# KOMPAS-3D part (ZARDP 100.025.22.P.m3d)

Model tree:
1. Операция без истории:1
2. Операция без истории:2
3. Операция без истории:3
4. Операция без истории:4
5. Операция без истории:5
6. Операция без истории:6
7. Операция без истории:7
8. Операция без истории:8
9. Операция без истории:9
10. Операция без истории:10
11. Операция без истории:11
12. Операция без истории:12
13. Операция без истории:13
14. Операция без истории:14
15. Операция без истории:15
16. Операция без истории:16
17. Операция без истории:17
18. Операция без истории:18
19. Операция без истории:19
20. Операция без истории:20
21. Операция без истории:21
22. Операция без истории:22
23. Операция без истории:23
24. Операция без истории:24
25. Операция без истории:25
26. Операция без истории:26
27. Операция без истории:27
28. Операция без истории:28
29. Операция без истории:29
30. Операция без истории:30
31. Операция без истории:31
32. Операция без истории:32
33. Операция без истории:33
34. Операция без истории:34
35. Операция без истории:35
36. Операция без истории:36
37. Операция без истории:37
38. Операция без истории:38
39. Операция без истории:39
40. Операция без истории:40
41. Операция без истории:41
42. Операция без истории:42
43. Операция без истории:43
44. Операция без истории:44
45. Операция без истории:45
46. Операция без истории:46
47. Операция без истории:47
48. Операция без истории:48
49. Операция без истории:49
50. Операция без истории:50
51. Операция без истории:51
52. Операция без истории:52
53. Операция без истории:53
54. Операция без истории:54
55. Операция без истории:55
56. Операция без истории:56
57. Операция без истории:57
58. Операция без истории:58
59. Операция без истории:59
60. Операция без истории:60
61. Операция без истории:61
62. Операция без истории:62
63. Операция без истории:63

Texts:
  ЗАРДП.100.025.22-Р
